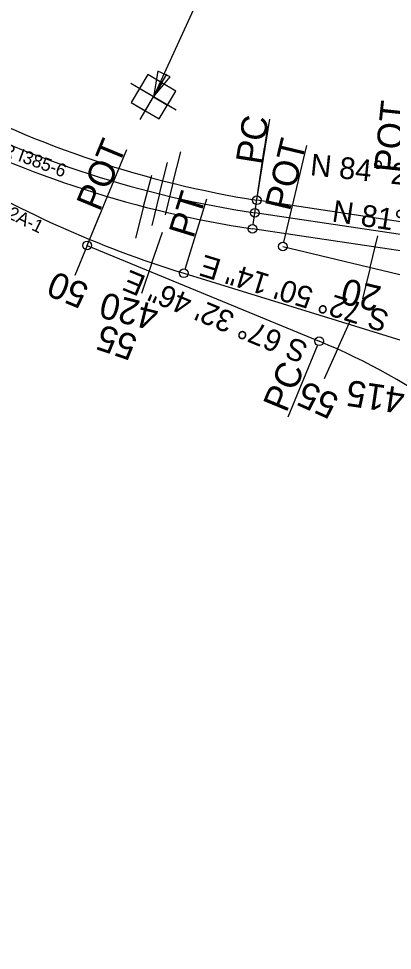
# Model space of a CAD drawing. Extents: x 1603447 to 1622636, y 1083818 to 1103958.
# Drawn here: x 1608552 to 1609242, y 1093148 to 1094869 of the extents above; entities that cross this region are included whole.
import ezdxf

# ---------------------------------------------------------------- set-up
doc = ezdxf.new("R2010")
doc.units = 0
for name, color, linetype in [('Level 1', 7, 'Continuous'), ('RD_HC_Points', 7, 'Continuous'), ('RD_HC_SUR_Bearing_TX400', 7, 'Continuous'), ('RD_HC_SUR_CL400', 7, 'Continuous'), ('RD_HC_SUR_PC_PT_400', 7, 'Continuous'), ('RD_HC_SUR_Tic400', 7, 'Continuous'), ('RD_HC_SUR_TX_Sta400', 7, 'Continuous'), ('RD_SHT_Misc1', 7, 'Continuous'), ('RD_TX_Misc1', 7, 'Continuous')]:
    doc.layers.add(name, color=color, linetype=linetype)

msp = doc.modelspace()

# ---------------------------------------------------------------- linework, layer by layer
at = {"layer": 'Level 1'}
for p, q in [((1608681.5, 1094457.6), (1608751.5, 1094627.1)), ((1609103.8, 1094265.7), (1609048.9, 1094132.9))]:
    msp.add_line(p, q, dxfattribs=at)
for centre in [(1608678.4, 1094450.2), (1609106.9, 1094273.1)]:
    msp.add_circle(centre, 8, dxfattribs=at)
at = {"layer": 'RD_HC_Points'}
msp.add_lwpolyline([(1608993.9, 1095083.3), (1608947.8, 1095046.6), (1608800.8, 1094724.6)], dxfattribs=at)
msp.add_lwpolyline([(1608808.7, 1094772), (1608800.8, 1094724.6), (1608831.3, 1094761.7)], close=True, dxfattribs=at)
at = {"layer": 'RD_HC_SUR_CL400'}
for p, q in [((1609716.2, 1094425.3), (1608991.5, 1094533.5)), ((1609712.8, 1094402.3), (1608988, 1094510.5)), ((1609691.8, 1094375.1), (1608983.5, 1094480.9)), ((1608678.4, 1094450.2), (1609106.9, 1094273.1)), ((1609039.4, 1094448.2), (1609788.6, 1094268.5)), ((1608856.7, 1094398.7), (1609307.8, 1094259.4))]:
    msp.add_line(p, q, dxfattribs=at)
for centre, radius, start, end in [((1609289.4, 1096392.5), 1882.8, 242.0082, 260.8939), ((1609270, 1096399.4), 1909.9, 242.6268, 261.5065), ((1609270, 1096399.4), 1939.9, 242.6268, 261.5065), ((1609446.9, 1096309.6), 2000, 238.6268, 252.8371), ((1608648.5, 1093164.1), 1200, 40.4045, 67.546), ((1607990.9, 1094380.3), 2000, 306.4947, 324.5024)]:
    msp.add_arc(centre, radius, start, end, dxfattribs=at)
at = {"layer": 'RD_HC_SUR_PC_PT_400'}
for p, q in [((1608992.7, 1094541.4), (1609015.5, 1094683.4)), ((1608989.1, 1094518.4), (1609010.4, 1094660.6)), ((1608984.7, 1094488.8), (1609005.9, 1094631)), ((1609041.3, 1094456), (1609084.1, 1094634.4)), ((1608859.1, 1094406.3), (1608899.1, 1094536.1))]:
    msp.add_line(p, q, dxfattribs=at)
for centre in [(1608991.5, 1094533.5), (1608988, 1094510.5), (1608983.5, 1094480.9), (1609039.4, 1094448.2), (1608856.7, 1094398.7)]:
    msp.add_circle(centre, 8, dxfattribs=at)
at = {"layer": 'RD_HC_SUR_Tic400'}
for p, q in [((1608552.5, 1094660), (1608552.5, 1094660)), ((1608645.6, 1094623.3), (1608645.6, 1094623.3)), ((1608836.8, 1094565), (1608851.2, 1094623.2)), ((1608620.8, 1094603.3), (1608620.8, 1094603.3)), ((1608740.4, 1094591.6), (1608740.4, 1094591.6)), ((1608812.1, 1094545.3), (1608826.5, 1094603.5)), ((1608592, 1094581.9), (1608592, 1094581.9)), ((1608782.6, 1094521.8), (1608797.7, 1094579.9)), ((1608715.7, 1094571.8), (1608715.7, 1094571.8)), ((1608836.8, 1094565), (1608822.4, 1094506.8)), ((1608686.5, 1094549.4), (1608686.5, 1094549.4)), ((1608812.1, 1094545.3), (1608797.7, 1094487)), ((1608934.4, 1094543.5), (1608934.4, 1094543.5)), ((1608909.7, 1094523.9), (1608909.7, 1094523.9)), ((1609033.1, 1094527.3), (1609033.1, 1094527.3)), ((1608678.4, 1094450.2), (1608701.3, 1094505.6)), ((1608782.6, 1094521.8), (1608767.5, 1094463.7)), ((1609008.4, 1094507.5), (1609008.4, 1094507.5)), ((1609132, 1094512.5), (1609132, 1094512.5)), ((1608612.4, 1094492.1), (1608612.4, 1094492.1)), ((1608880, 1094499.2), (1608880, 1094499.2)), ((1609107.3, 1094492.7), (1609107.3, 1094492.7)), ((1609230.9, 1094497.7), (1609230.9, 1094497.7)), ((1608798, 1094417.8), (1608817.5, 1094474.6)), ((1608978.4, 1094481.6), (1608978.4, 1094481.6)), ((1609206.2, 1094477.9), (1609206.2, 1094477.9)), ((1609077.3, 1094466.8), (1609077.3, 1094466.8)), ((1609200.9, 1094409.5), (1609214.9, 1094467.8)), ((1608678.4, 1094450.2), (1608655.5, 1094394.7)), ((1608704.3, 1094452.6), (1608704.3, 1094452.6)), ((1609176.2, 1094452.1), (1609176.2, 1094452.1)), ((1609103.6, 1094432.8), (1609103.6, 1094432.8)), ((1608770.8, 1094412), (1608770.8, 1094412)), ((1608798, 1094417.8), (1608778.5, 1094361.1)), ((1609200.9, 1094409.5), (1609186.9, 1094351.2)), ((1608893.3, 1094387.4), (1608893.3, 1094387.4)), ((1608863.2, 1094373.8), (1608863.2, 1094373.8)), ((1608988.8, 1094357.9), (1608988.8, 1094357.9)), ((1608955.7, 1094335.6), (1608955.7, 1094335.6)), ((1609084.4, 1094328.4), (1609084.4, 1094328.4)), ((1609140.3, 1094258.7), (1609164.9, 1094313.4)), ((1609179.9, 1094298.9), (1609179.9, 1094298.9)), ((1609048.1, 1094297.4), (1609048.1, 1094297.4)), ((1609140.3, 1094258.7), (1609115.7, 1094204)), ((1609229.7, 1094214), (1609229.7, 1094214))]:
    msp.add_line(p, q, dxfattribs=at)
at = {"layer": 'RD_SHT_Misc1'}
for p, q in [((1608776, 1094682.7), (1608825.5, 1094766.6)), ((1608842.7, 1094699.9), (1608758.8, 1094749.4)), ((1608816, 1094750.5), (1608800.8, 1094724.6)), ((1608800.8, 1094724.6), (1608774.9, 1094739.9)), ((1608785.5, 1094698.8), (1608800.8, 1094724.6)), ((1608800.8, 1094724.6), (1608826.6, 1094709.4))]:
    msp.add_line(p, q, dxfattribs=at)
msp.add_lwpolyline([(1608841.8, 1094735.2), (1608790.2, 1094765.7), (1608759.7, 1094714.1), (1608811.3, 1094683.6)], close=True, dxfattribs=at)
for points in [[(1608841.8, 1094735.2), (1608816, 1094750.5)], [(1608774.9, 1094739.9), (1608759.7, 1094714.1), (1608785.5, 1094698.8)], [(1608826.6, 1094709.4), (1608841.8, 1094735.2)]]:
    msp.add_lwpolyline(points, dxfattribs=at)

# ---------------------------------------------------------------- texts
at = {"layer": 'Level 1'}
for s, rotation, p in [('POT', 67.546, (1608701.4, 1094511)), ('50', 157.546, (1608684.6, 1094376.4)), ('55', 161.0689, (1608774.1, 1094282)), ('PC', 67.546, (1609046.1, 1094139.7)), ('55', 155.8078, (1609146.2, 1094171.7)), ('415', 171.5065, (1609266.9, 1094186.1))]:
    msp.add_text(s, height=48, rotation=rotation, dxfattribs=at).set_placement(p)
at = {"layer": 'RD_HC_SUR_Bearing_TX400'}
for s, rotation, p in [('N 84%%d 22\' 08" W', 353.9996, (1609088.9, 1094579.9)), ('N 81%%d 30\' 24" W', 351.5065, (1609128.8, 1094494.5)), ('S 72%%d 50\' 14" E', 162.8371, (1609238.2, 1094327.4)), ('S 67%%d 32\' 46" E', 157.546, (1609088.7, 1094268.4))]:
    msp.add_text(s, height=40, rotation=rotation, dxfattribs=at).set_placement(p)
at = {"layer": 'RD_HC_SUR_PC_PT_400'}
for s, rotation, p in [('POT', 83.9996, (1609255.2, 1094582.9)), ('PC', 80.8939, (1608999.8, 1094598)), ('POT', 76.5065, (1609052.6, 1094511.9)), ('PT', 72.8371, (1608874, 1094461.4))]:
    msp.add_text(s, height=48, rotation=rotation, dxfattribs=at).set_placement(p)
at = {"layer": 'RD_HC_SUR_TX_Sta400'}
for s, rotation, p in [('20', 166.5065, (1609224, 1094373.5)), ('420', 166.1259, (1608813.2, 1094338.8))]:
    msp.add_text(s, height=48, rotation=rotation, dxfattribs=at).set_placement(p)
at = {"layer": 'RD_TX_Misc1'}
for s, rotation, p in [('CUR I385-6', 339.8242, (1608475.4, 1094633.9)), ('RAMP_2A-1', 333.8067, (1608430.1, 1094550.5))]:
    msp.add_text(s, height=24, rotation=rotation, dxfattribs=at).set_placement(p)

doc.saveas('drawing.dxf')
